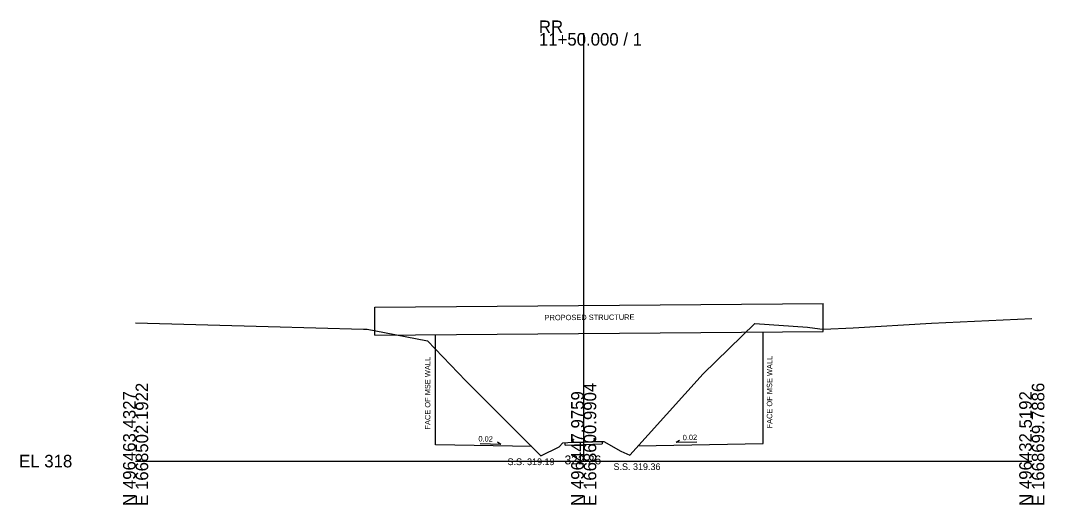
# Model space of a CAD drawing. Extents: x -26 to 203, y -10 to 3083.
# Drawn here: x -25.7 to 202.8, y 1490.3 to 1598.3 of the extents above; entities that cross this region are included whole.
import ezdxf

# ---------------------------------------------------------------- set-up
doc = ezdxf.new("R2010")
doc.units = 0
for name, color, linetype in [('Default', 7, 'Continuous'), ('Exist Cross Section Cell', 7, 'Continuous'), ('Exist XS Center Line Elevation Label', 7, 'Continuous'), ('Exist XS Ground Line', 7, 'Continuous'), ('Prop Retaining Wall', 7, 'Continuous'), ('Prop XS Bridge', 7, 'Continuous'), ('Prop XS Finish Grade Earthwork', 7, 'Continuous'), ('Prop XS Label Text', 7, 'Continuous'), ('Prop XS SS Elevation Text', 7, 'Continuous'), ('Prop XS Subgrade', 7, 'Continuous')]:
    doc.layers.add(name, color=color, linetype=linetype)

msp = doc.modelspace()

# ---------------------------------------------------------------- linework, layer by layer
at = {"layer": 'Default'}
for p, q in [((97.34, 1504.29), (97.34, 1504.16)), ((97.38, 1504.32), (97.53, 1504.32)), ((97.46, 1504.84), (97.46, 1504.77)), ((97.48, 1504.86), (97.7, 1504.86)), ((97.48, 1504.75), (97.55, 1504.75)), ((97.57, 1504.74), (97.57, 1504.35)), ((97.61, 1504.74), (97.61, 1504.35)), ((97.63, 1504.75), (97.7, 1504.75)), ((97.65, 1504.32), (97.8, 1504.32)), ((97.72, 1504.84), (97.72, 1504.77)), ((97.84, 1504.29), (97.84, 1504.18)), ((102.13, 1504.45), (102.13, 1504.33)), ((102.16, 1504.49), (102.32, 1504.49)), ((102.25, 1505.01), (102.25, 1504.94)), ((102.27, 1505.02), (102.49, 1505.02)), ((102.27, 1504.92), (102.34, 1504.92)), ((102.35, 1504.9), (102.35, 1504.52)), ((102.4, 1504.9), (102.4, 1504.52)), ((102.42, 1504.92), (102.49, 1504.92)), ((102.43, 1504.49), (102.59, 1504.49)), ((102.5, 1505.01), (102.5, 1504.94)), ((102.62, 1504.45), (102.62, 1504.35))]:
    msp.add_line(p, q, dxfattribs=at)
for centre, radius, start, end in [((97.38, 1504.29), 0.0324, 90, 180), ((97.48, 1504.84), 0.0162, 90, 180), ((97.48, 1504.77), 0.0162, 180, 270), ((97.53, 1504.35), 0.0324, 270, 360), ((97.55, 1504.74), 0.0162, 0, 90), ((97.63, 1504.74), 0.0162, 90, 180), ((97.65, 1504.35), 0.0324, 180, 270), ((97.7, 1504.84), 0.0162, 0, 90), ((97.7, 1504.77), 0.0162, 270, 360), ((97.8, 1504.29), 0.0324, 0, 90), ((102.16, 1504.45), 0.0324, 90, 180), ((102.27, 1505.01), 0.0162, 90, 180), ((102.27, 1504.94), 0.0162, 180, 270), ((102.32, 1504.52), 0.0324, 270, 360), ((102.34, 1504.9), 0.0162, 0, 90), ((102.42, 1504.9), 0.0162, 90, 180), ((102.43, 1504.52), 0.0324, 180, 270), ((102.49, 1505.01), 0.0162, 0, 90), ((102.49, 1504.94), 0.0162, 270, 360), ((102.59, 1504.45), 0.0324, 0, 90)]:
    msp.add_arc(centre, radius, start, end, dxfattribs=at)
at = {"layer": 'Exist Cross Section Cell'}
for p, q in [((100, 1500), (100, 1595.54)), ((0, 1500), (100, 1500)), ((100, 1500), (200, 1500))]:
    msp.add_line(p, q, dxfattribs=at)
at = {"layer": 'Exist XS Ground Line'}
msp.add_lwpolyline([(0, 1530.88), (29.6, 1530.03), (50.89, 1529.41), (51.64, 1529.42), (55.53, 1528.68), (65.13, 1526.83), (73.69, 1517.9), (90.47, 1501.19), (94.51, 1503.21), (95.38, 1504.09), (97.59, 1504.2), (99.43, 1504.24), (100, 1504.26), (102.38, 1504.34), (104.48, 1504.41), (108.31, 1502.25), (110.28, 1501.36), (126.63, 1519.44), (138.21, 1530.73), (149.92, 1529.86), (152.73, 1529.53), (153.55, 1529.46), (160.12, 1529.77), (177.62, 1530.79), (200, 1531.85)], dxfattribs=at)
at = {"layer": 'Prop Retaining Wall'}
for p, q in [((66.93, 1503.66), (66.93, 1528.22)), ((140.02, 1503.95), (140.02, 1528.84))]:
    msp.add_line(p, q, dxfattribs=at)
at = {"layer": 'Prop XS Bridge'}
for p, q in [((53.42, 1534.36), (153.42, 1535.2)), ((53.42, 1528.11), (53.42, 1534.36)), ((153.42, 1528.95), (153.42, 1535.2)), ((53.42, 1528.11), (153.42, 1528.95))]:
    msp.add_line(p, q, dxfattribs=at)
at = {"layer": 'Prop XS Finish Grade Earthwork'}
for p, q in [((112.12, 1503.4), (140.02, 1503.95)), ((88.42, 1503.23), (66.93, 1503.66))]:
    msp.add_line(p, q, dxfattribs=at)
at = {"layer": 'Prop XS SS Elevation Text'}
for p, q in [((81.52, 1503.74), (76.86, 1503.84)), ((81.52, 1503.74), (80.73, 1504.22)), ((120.6, 1504.19), (121.39, 1504.66)), ((120.6, 1504.19), (125.26, 1504.28))]:
    msp.add_line(p, q, dxfattribs=at)
at = {"layer": 'Prop XS Subgrade'}
for p, q in [((95.87, 1503.54), (95.87, 1504.11)), ((95.87, 1503.54), (104.1, 1503.83)), ((104.1, 1504.4), (104.1, 1503.83))]:
    msp.add_line(p, q, dxfattribs=at)

# ---------------------------------------------------------------- texts
at = {"layer": 'Exist Cross Section Cell'}
for s, p in [('RR', (90, 1595.54)), ('11+50.000 / 1', (90, 1592.74)), ('EL 318', (-26, 1498.6))]:
    msp.add_text(s, height=2.8, dxfattribs=at).set_placement(p)
for s, p in [('N 496463.4327', (0, 1490)), ('E 1668502.1922', (2.8, 1490)), ('N 496447.9759', (100, 1490)), ('E 1668600.9904', (102.8, 1490)), ('N 496432.5192', (200, 1490)), ('E 1668699.7886', (202.8, 1490))]:
    msp.add_text(s, height=2.8, rotation=90, dxfattribs=at).set_placement(p)
at = {"layer": 'Exist XS Center Line Elevation Label'}
msp.add_text('322.26', height=2, dxfattribs=at).set_placement((95.73, 1499.26))
at = {"layer": 'Prop XS Label Text'}
for s, rotation, p in [('PROPOSED STRUCTURE', 0.3079, (91.27, 1531.43)), ('FACE OF MSE WALL', 90, (65.77, 1507.05)), ('FACE OF MSE WALL', 90, (142.07, 1507.29))]:
    msp.add_text(s, height=1.2, rotation=rotation, dxfattribs=at).set_placement(p)
at = {"layer": 'Prop XS SS Elevation Text'}
for rotation, p in [(358.8542, (76.49, 1504.39)), (1.1458, (122.11, 1504.65))]:
    msp.add_text('0.02', height=1.2, rotation=rotation, dxfattribs=at).set_placement(p)
for s, p in [('S.S. 319.19', (83.01, 1499.1)), ('S.S. 319.36', (106.65, 1498))]:
    msp.add_text(s, height=1.5, dxfattribs=at).set_placement(p)

doc.saveas('drawing.dxf')
